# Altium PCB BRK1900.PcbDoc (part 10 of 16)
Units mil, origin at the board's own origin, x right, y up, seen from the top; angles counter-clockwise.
Board outline 8858.27 x 5905.51 mil, 10 copper layers (L1-TOP, L2-GND, L3-PWR, L4-GND, L5-PWR, L6-PWR, L7-GND, L8-SIG, L9-GND, L10-BOT), stack 48.824 mil thick; 456 components, 571 nets, 2296 pads, 2416 vias.
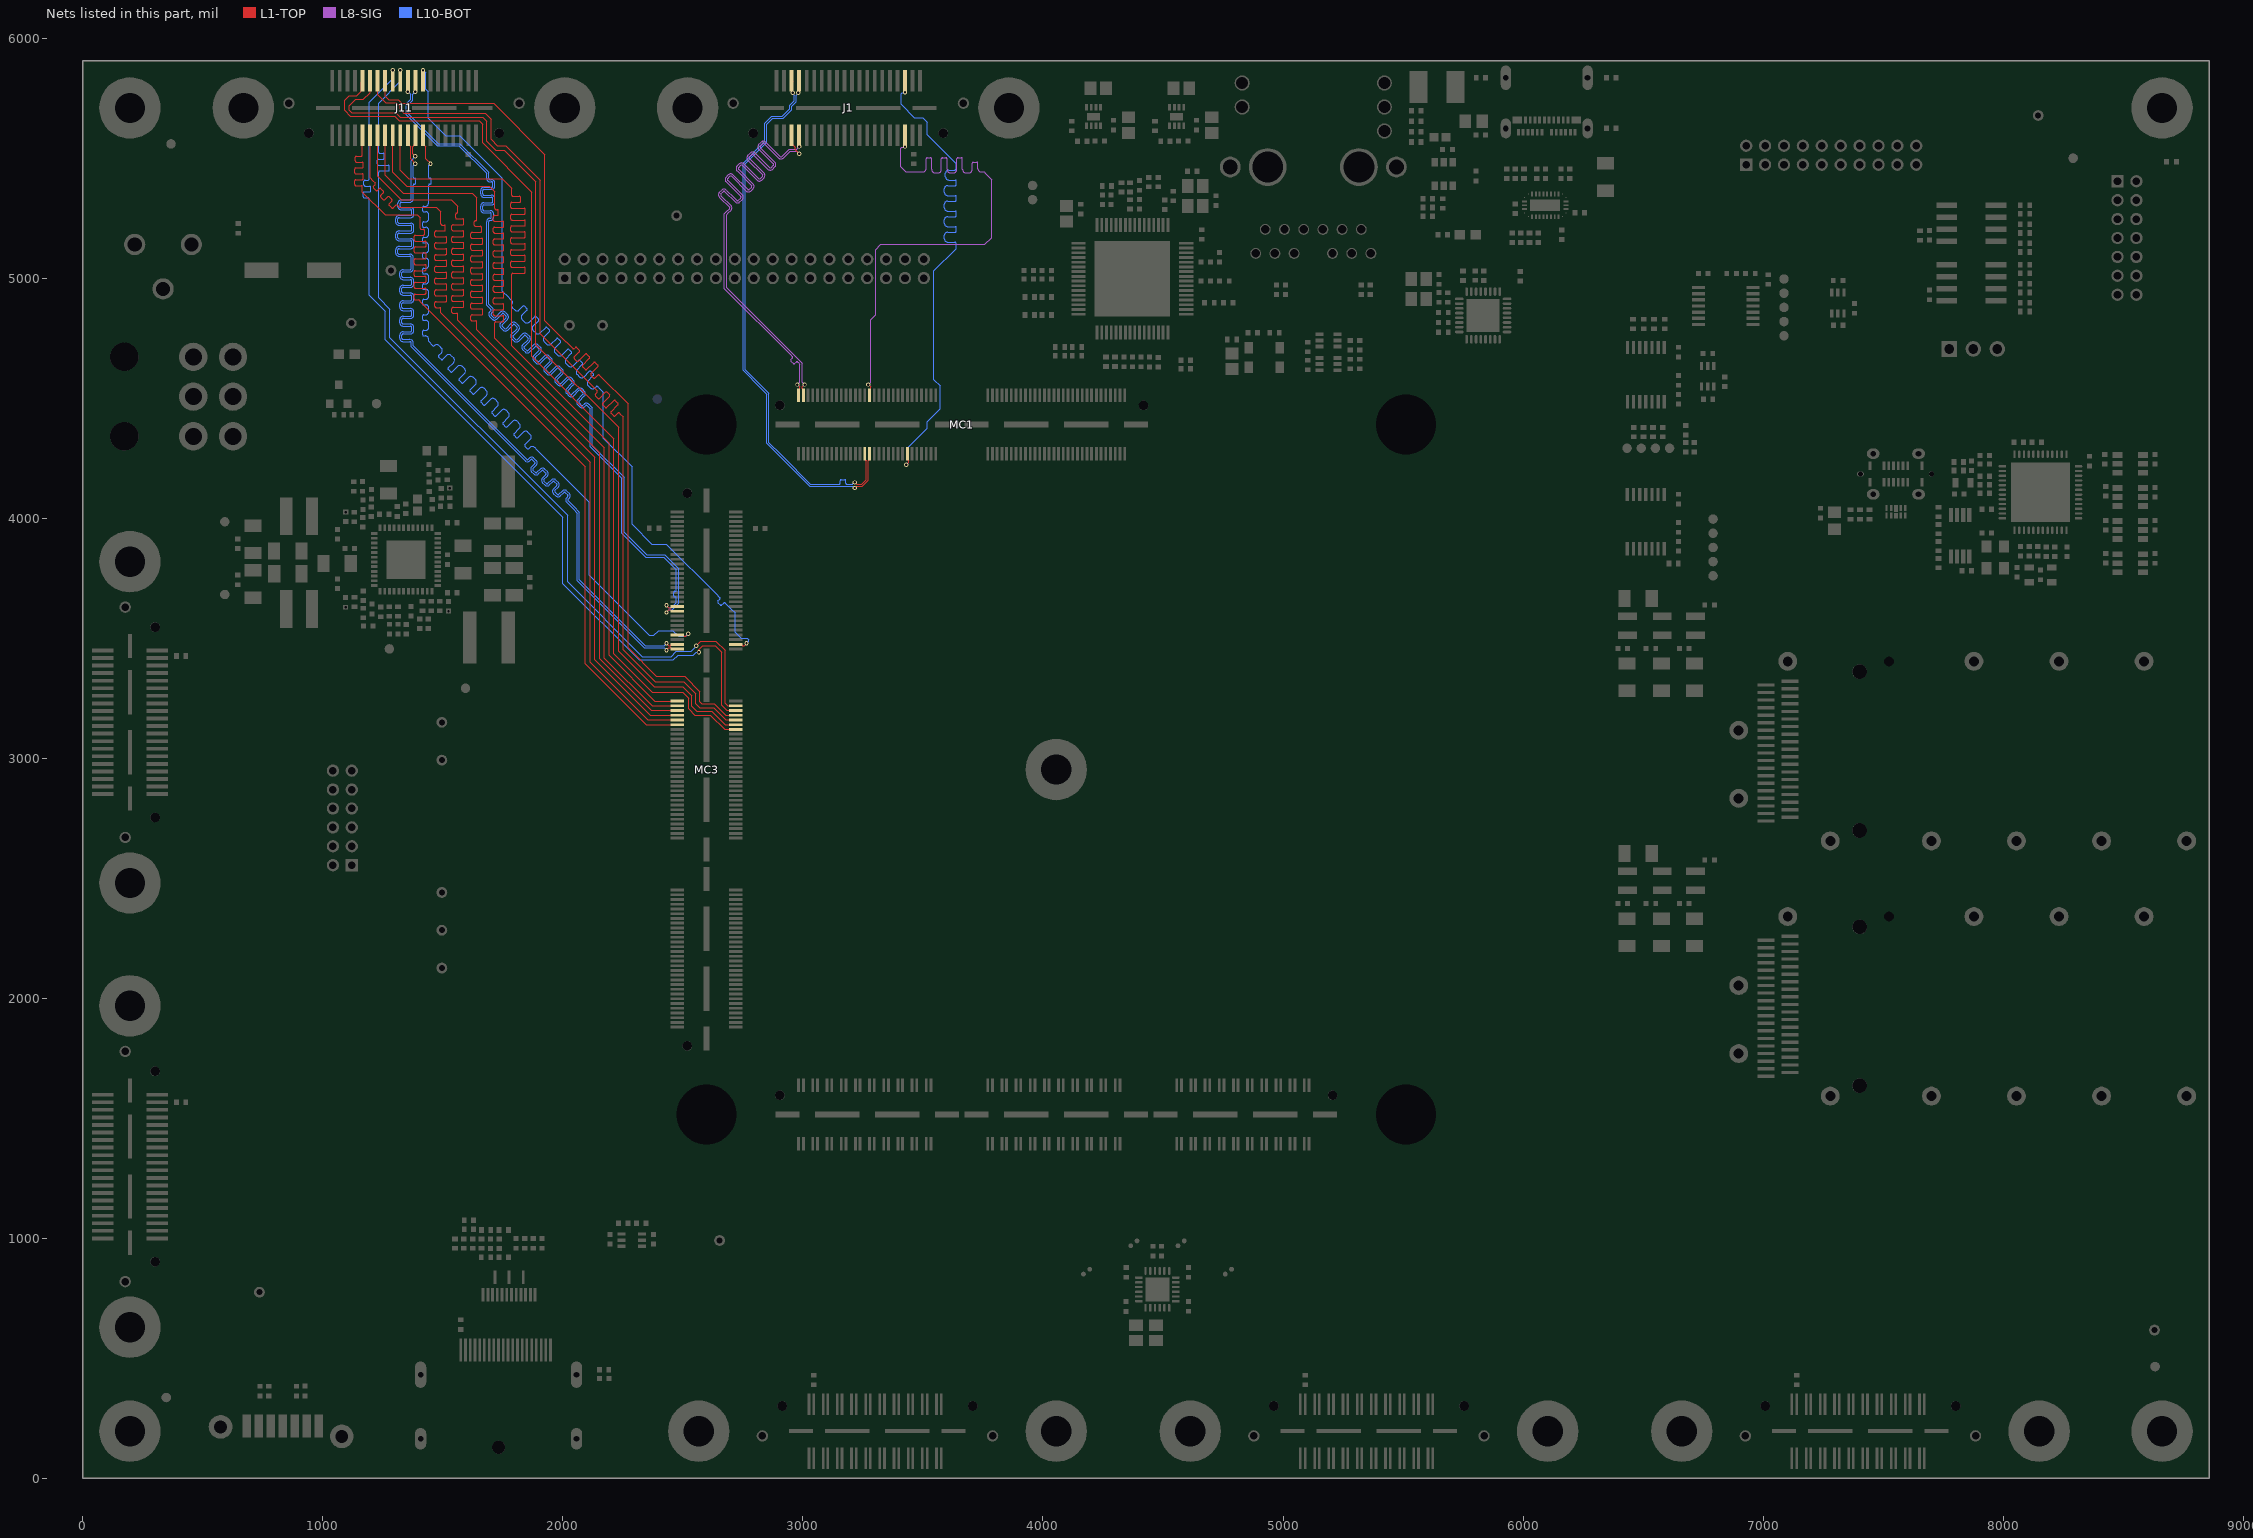
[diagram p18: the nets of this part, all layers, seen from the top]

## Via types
v1: diameter 18, hole 10, L1-TOP to L10-BOT, tented both sides, 2170 vias
v2: diameter 20, hole 10, L1-TOP to L10-BOT, tented both sides, 246 vias

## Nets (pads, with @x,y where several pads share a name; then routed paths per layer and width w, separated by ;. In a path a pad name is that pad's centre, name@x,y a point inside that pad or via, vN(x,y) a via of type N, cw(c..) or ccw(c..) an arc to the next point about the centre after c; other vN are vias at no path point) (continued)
SZG_PORTC_S10_D4N: J11.15 MC3.124 | length 3725.7
  L1-TOP w3.3: MC3.124@2720.08,3474.41 2742.72,3474.41 2748.11,3469.02 2756.01,3469.02 2765.08,3478.09 v1@2765.08,3478.35
  L10-BOT w3.3: v1@1418.37,5866.17 1428.63,5855.9 1428.63,5787.27 1439,5776.9 1439,5666.27 1513.27,5592 1571,5592 1748.03,5414.97 1748.03,4944.88 1758.16,4934.76 1761.19,4931.73 1789.71,4903.2 cw(c1786.42,4899.91) 1789.71,4896.61 ccw(c1799.37,4886.95) 1789.74,4877.27 ; 1789.74,4877.26 1799.57,4867.44 ccw(c1809.26,4877.07) 1818.91,4867.41 1833.95,4882.44 cw(c1837.24,4879.15) 1840.54,4882.44 1850.42,4872.55 cw(c1847.13,4869.26) 1850.42,4865.96 1829.35,4844.89 1829.35,4844.68 ccw(c1840.33,4836.55) 1830.69,4826.87 1840.52,4817.03 ccw(c1850.21,4826.67) 1859.87,4817.01 1882.25,4839.38 cw(c1885.57,4836.11) 1888.86,4839.41 1898.75,4829.52 cw(c1895.45,4826.23) 1898.75,4822.93 1875.03,4799.21 1875.03,4799 ccw(c1886,4790.87) 1876.37,4781.19 1886.2,4771.36 ccw(c1895.89,4780.99) 1905.55,4771.33 1927.93,4793.71 ; 1927.95,4793.73 cw(c1931.25,4790.43) 1934.54,4793.73 1944.43,4783.84 cw(c1941.13,4780.55) 1944.43,4777.25 1920.71,4753.53 1920.71,4753.32 ccw(c1931.68,4745.19) 1922.05,4735.51 1931.88,4725.68 ccw(c1941.57,4735.31) 1951.23,4725.65 1973.61,4748.03 ; 1973.63,4748.05 cw(c1976.92,4744.75) 1980.22,4748.05 1990.1,4738.16 cw(c1986.81,4734.87) 1990.1,4731.57 1966.39,4707.85 1966.39,4707.64 ccw(c1977.36,4699.51) 1967.73,4689.83 1977.56,4680 ccw(c1987.25,4689.63) 1996.91,4679.97 2019.29,4702.35 ; 2019.31,4702.37 cw(c2022.6,4699.08) 2025.9,4702.37 2035.78,4692.49 cw(c2032.49,4689.19) 2035.78,4685.9 2012.06,4662.18 2012.06,4661.96 ccw(c2023.04,4653.83) 2013.41,4644.15 2023.24,4634.32 ; 2023.24,4634.32 ccw(c2032.93,4643.95) 2042.59,4634.29 2064.96,4656.67 ; 2064.99,4656.69 cw(c2068.28,4653.4) 2071.58,4656.69 2081.46,4646.81 cw(c2078.17,4643.51) 2081.46,4640.22 2057.74,4616.5 2057.74,4616.29 ccw(c2068.72,4608.16) 2059.09,4598.47 2068.92,4588.64 ccw(c2078.61,4598.27) 2088.26,4588.61 2110.64,4610.99 cw(c2113.96,4607.72) 2117.26,4611.01 2127.14,4601.13 cw(c2123.85,4597.83) 2127.14,4594.54 2103.42,4570.82 2103.42,4570.61 ccw(c2114.4,4562.48) 2104.77,4552.79 2114.6,4542.96 ccw(c2124.28,4552.59) 2133.94,4542.93 2138.67,4547.66 cw(c2141.96,4544.36) 2145.27,4547.64 ; 2145.29,4547.63 2146.58,4546.34 2149.61,4543.31 2169.29,4523.62 2169.29,4333.73 2289,4214.02 2289,3974.27 2371.27,3892 2431,3892 2635.96,3687.04 2653.6,3669.4 cw(c2650.31,3666.1) 2653.6,3662.81 2645.92,3655.12 ccw(c2649.22,3651.83) 2645.92,3648.53 2655.81,3638.65 ccw(c2659.1,3641.94) 2662.4,3638.65 2670.08,3646.33 cw(c2673.37,3643.04) 2676.67,3646.33 2700.06,3622.94 2717.23,3605.77 2717.23,3569.91 2717.23,3525.05 2742.27,3500 2769,3500 2775,3494 2775,3488.27 v1@2765.08,3478.35
  other v1: 2765.08,3479.35 1417.37,5866.17
SZG_PORTC_S11_D5N: J11.16 MC3.127 | length 3773.6
  L1-TOP w3.3: J11.16@1417.38,5595.86 1417.38,5559 1428.63,5547.75 1428.63,5498 v1@1448.88,5477.75 ; MC3.127@2476.77,3513.78 2499.41,3513.78 2504.8,3508.39 2512.7,3508.39 2521.77,3517.46 v1@2521.77,3517.72
  L10-BOT w3.3: v1@1448.88,5477.75 1441,5469.87 1441,5437.01 1441,5419.78 ccw(c1445.66,5419.78) 1445.66,5415.12 1447.7,5415.12 cw(c1447.7,5410.46) 1452.36,5410.46 1452.36,5396.48 cw(c1447.7,5396.48) 1447.7,5391.82 1445.66,5391.82 ccw(c1445.66,5387.16) 1441,5387.16 1441,5362.2 1441,5354.33 1441,5312.98 cw(c1427.34,5312.98) 1427.34,5299.32 1420.66,5299.32 ccw(c1420.66,5294.66) 1416,5294.66 1416,5280.68 ccw(c1420.66,5280.68) 1420.66,5276.02 1428.27,5276.02 cw(c1428.27,5262.36) 1441.93,5262.36 1441.93,5248.38 cw(c1428.27,5248.38) 1428.27,5234.72 1420.66,5234.72 ccw(c1420.66,5230.06) 1416,5230.06 1416,5216.08 ccw(c1420.66,5216.08) 1420.66,5211.42 1428.27,5211.42 cw(c1428.27,5197.76) 1441.93,5197.76 1441.93,5183.78 cw(c1428.27,5183.78) 1428.27,5170.12 1420.66,5170.12 ccw(c1420.66,5165.46) 1416,5165.46 1416,5151.48 ccw(c1420.66,5151.48) 1420.66,5146.82 1428.27,5146.82 cw(c1428.27,5133.16) 1441.93,5133.16 1441.93,5119.18 cw(c1428.27,5119.18) 1428.27,5105.52 1420.66,5105.52 ccw(c1420.66,5100.86) 1416,5100.86 1416,5086.88 ccw(c1420.66,5086.88) 1420.66,5082.22 1428.27,5082.22 cw(c1428.27,5068.56) 1441.93,5068.56 1441.93,5054.58 cw(c1428.27,5054.58) 1428.27,5040.92 1420.66,5040.92 ccw(c1420.66,5036.26) 1416,5036.26 1416,5022.28 ccw(c1420.66,5022.28) 1420.66,5017.62 1428.27,5017.62 cw(c1428.27,5003.96) 1441.93,5003.96 1441.93,4989.98 cw(c1428.27,4989.98) 1428.27,4976.32 1420.66,4976.32 ccw(c1420.66,4971.66) 1416,4971.66 1416,4957.68 ccw(c1420.66,4957.68) 1420.66,4953.02 1428.27,4953.02 cw(c1428.27,4939.36) 1441.93,4939.36 1441.93,4925.38 cw(c1428.27,4925.38) 1428.27,4911.72 1420.66,4911.72 ccw(c1420.66,4907.06) 1416,4907.06 1416,4893.08 ccw(c1420.66,4893.08) 1420.66,4888.42 1428.27,4888.42 cw(c1428.27,4874.76) 1441.93,4874.76 1441.93,4860.78 cw(c1428.27,4860.78) 1428.27,4847.12 1420.66,4847.12 ccw(c1420.66,4842.46) 1416,4842.46 1416,4828.48 ccw(c1420.66,4828.48) 1420.66,4823.82 1428.27,4823.82 cw(c1428.27,4810.16) 1441.93,4810.16 1441.93,4796.18 cw(c1428.27,4796.18) 1428.27,4782.52 1420.66,4782.52 ccw(c1420.66,4777.86) 1416,4777.86 1416,4763.88 ccw(c1420.66,4763.88) 1420.66,4759.22 1427.34,4759.22 cw(c1427.34,4745.56) 1441,4745.56 1441,4739.41 1441,4736.17 1447.32,4729.85 1450.35,4726.82 1458.77,4718.4 ccw(c1462.06,4721.69) 1465.36,4718.4 cw(c1475.02,4708.74) 1484.68,4718.4 1494.56,4708.51 cw(c1484.9,4698.86) 1494.58,4689.22 1483.21,4677.84 ccw(c1486.5,4674.55) 1483.21,4671.25 1493.09,4661.37 ccw(c1496.39,4664.66) 1499.68,4661.37 1517.08,4678.76 1517.29,4678.76 cw(c1525.42,4667.78) 1535.08,4677.44 1544.96,4667.56 cw(c1535.3,4657.9) 1545,4648.27 1522.58,4625.86 ; 1522.56,4625.84 ccw(c1525.86,4622.54) 1522.56,4619.25 1532.45,4609.36 ccw(c1535.74,4612.66) 1539.04,4609.36 1562.76,4633.08 1562.97,4633.08 cw(c1571.1,4622.11) 1580.76,4631.76 1590.64,4621.88 cw(c1580.98,4612.22) 1590.68,4602.59 1568.26,4580.18 ; 1568.24,4580.16 ccw(c1571.54,4576.86) 1568.24,4573.57 1578.13,4563.68 ccw(c1581.42,4566.98) 1584.72,4563.68 1608.44,4587.4 1608.65,4587.4 cw(c1616.78,4576.43) 1626.43,4586.09 1636.32,4576.2 cw(c1626.66,4566.54) 1636.35,4556.92 1613.94,4534.5 ; 1613.92,4534.48 ccw(c1617.21,4531.19) 1613.92,4527.89 1623.8,4518.01 ccw(c1627.1,4521.3) 1630.39,4518.01 1654.11,4541.72 1654.33,4541.72 cw(c1662.46,4530.75) 1672.11,4540.41 1682,4530.52 cw(c1672.34,4520.86) 1682.03,4511.24 1659.62,4488.82 ; 1659.6,4488.8 ccw(c1662.89,4485.51) 1659.6,4482.21 1669.48,4472.33 ccw(c1672.78,4475.62) 1676.07,4472.33 1699.79,4496.05 1700,4496.05 cw(c1708.13,4485.07) 1717.79,4494.73 1727.68,4484.84 cw(c1718.02,4475.18) 1727.71,4465.56 1705.3,4443.15 ccw(c1708.57,4439.83) 1705.28,4436.53 1715.16,4426.65 ccw(c1718.46,4429.94) 1721.75,4426.65 1745.47,4450.37 1745.68,4450.37 cw(c1753.81,4439.39) 1763.47,4449.05 1773.36,4439.16 cw(c1763.7,4429.5) 1773.39,4419.88 1750.98,4397.47 ; 1750.96,4397.44 ccw(c1754.25,4394.15) 1750.96,4390.85 1760.84,4380.97 ccw(c1764.14,4384.26) 1767.43,4380.97 1791.15,4404.69 1791.36,4404.69 cw(c1799.49,4393.71) 1809.15,4403.37 1819.04,4393.48 cw(c1809.38,4383.83) 1819.07,4374.2 1796.66,4351.79 ; 1796.63,4351.77 ccw(c1799.93,4348.47) 1796.63,4345.18 1806.52,4335.29 ccw(c1809.82,4338.58) 1813.11,4335.29 1836.83,4359.01 1837.04,4359.01 cw(c1845.17,4348.03) 1854.83,4357.69 1864.72,4347.81 cw(c1855.06,4338.15) 1864.75,4328.52 1842.34,4306.11 ; 1842.31,4306.09 ccw(c1845.61,4302.79) 1842.31,4299.5 1852.2,4289.61 ccw(c1855.49,4292.91) 1858.79,4289.61 1863.51,4294.33 cw(c1873.17,4284.68) 1881.3,4295.65 1881.51,4295.65 1882.82,4294.35 ; 1882.83,4294.33 1884.15,4293.02 1887.18,4289.99 2110,4067.17 2110,3762.04 2360.08,3511.96 2379.61,3511.96 2399.53,3531.87 2458.82,3531.87 2482.25,3508.44 2512.49,3508.44 v1@2521.77,3517.72
  other v1: 2521.77,3518.72 1448.88,5476.75
SZG_PORTC_S12_D6P: J11.17 MC3.137 | length 3725.2
  L1-TOP w3.3: v1@2431.77,3608.27 2432.87,3608.27 2442.15,3617.55 2448.79,3617.55 2454.13,3612.2 MC3.137@2476.77,3612.2
  L10-BOT w3.3: v1@1384.89,5776.76 1374.63,5766.5 1374.63,5740.27 1357,5722.64 1357,5684 1481,5560 1570.73,5560 1688.66,5442.07 1691.3,5439.43 1691.3,5421.26 1691.3,5415.11 ccw(c1695.96,5415.11) 1695.96,5410.45 1702.64,5410.45 cw(c1702.64,5396.79) 1716.3,5396.79 1716.3,5382.81 cw(c1702.64,5382.81) 1702.64,5369.15 1670.96,5369.15 ccw(c1670.96,5364.49) 1666.3,5364.49 1666.3,5350.51 ccw(c1670.96,5350.51) 1670.96,5345.85 1702.64,5345.85 cw(c1702.64,5332.19) 1716.3,5332.19 1716.3,5318.21 cw(c1702.64,5318.21) 1702.64,5304.55 1670.96,5304.55 ccw(c1670.96,5299.89) 1666.3,5299.89 1666.3,5285.91 ccw(c1670.96,5285.91) 1670.96,5281.25 1697.81,5281.25 cw(c1697.81,5267.59) 1711.47,5267.59 1711.47,5253.61 cw(c1697.81,5253.61) 1697.81,5239.95 1695.96,5239.95 ccw(c1695.96,5235.29) 1691.3,5235.29 1691.3,5173.23 1691.3,4891.38 1694.33,4888.35 1706.63,4876.05 1707.95,4874.73 1707.95,4874.52 cw(c1696.97,4866.39) 1706.63,4856.73 1701.93,4852.03 ; 1701.91,4852 ccw(c1705.2,4848.71) 1701.91,4845.41 1711.79,4835.53 ccw(c1715.09,4838.82) 1718.38,4835.53 1742.1,4859.25 1742.31,4859.25 cw(c1750.44,4848.27) 1760.1,4857.93 1769.99,4848.05 cw(c1760.33,4838.39) 1770.02,4828.76 1747.61,4806.35 ccw(c1750.88,4803.03) 1747.59,4799.74 1757.47,4789.85 ccw(c1760.77,4793.15) 1764.06,4789.85 1787.78,4813.57 1787.99,4813.57 cw(c1796.12,4802.59) 1805.78,4812.25 1815.67,4802.37 cw(c1806.01,4792.71) 1815.7,4783.08 1793.29,4760.67 ; 1793.26,4760.65 ccw(c1796.56,4757.35) 1793.26,4754.06 1803.15,4744.17 ccw(c1806.45,4747.47) 1809.74,4744.17 1833.46,4767.89 1833.67,4767.89 cw(c1841.8,4756.91) 1851.46,4766.57 1861.34,4756.69 cw(c1851.69,4747.03) 1861.38,4737.4 1838.97,4714.99 ccw(c1842.24,4711.67) 1838.94,4708.38 1848.83,4698.49 ccw(c1852.12,4701.79) 1855.42,4698.49 1879.14,4722.21 1879.35,4722.21 cw(c1887.48,4711.23) 1897.14,4720.89 1907.02,4711.01 cw(c1897.36,4701.35) 1907.06,4691.72 1884.65,4669.31 ; 1884.62,4669.29 ccw(c1887.92,4665.99) 1884.62,4662.7 1894.51,4652.81 ccw(c1897.8,4656.11) 1901.1,4652.81 1924.82,4676.53 1925.03,4676.53 cw(c1933.16,4665.56) 1942.82,4675.21 1952.7,4665.33 cw(c1943.04,4655.67) 1952.74,4646.04 1930.32,4623.63 ; 1930.3,4623.61 ccw(c1933.6,4620.31) 1930.3,4617.02 1940.19,4607.13 ccw(c1943.48,4610.43) 1946.78,4607.13 1970.5,4630.85 1970.71,4630.85 cw(c1978.84,4619.88) 1988.5,4629.54 1998.38,4619.65 cw(c1988.72,4609.99) 1998.42,4600.37 1976,4577.95 ccw(c1979.28,4574.64) 1975.98,4571.34 1985.87,4561.46 ccw(c1989.16,4564.75) 1992.46,4561.46 2016.18,4585.17 2016.39,4585.17 cw(c2024.52,4574.2) 2034.18,4583.86 2044.06,4573.97 cw(c2034.4,4564.31) 2044.09,4554.69 2021.68,4532.27 ; 2021.66,4532.25 ccw(c2024.95,4528.96) 2021.66,4525.66 2031.54,4515.78 ccw(c2034.84,4519.07) 2038.13,4515.78 2061.85,4539.5 2062.07,4539.5 cw(c2070.2,4528.52) 2079.85,4538.18 2089.74,4528.29 cw(c2080.08,4518.63) 2089.77,4509.01 2067.36,4486.6 ccw(c2070.63,4483.28) 2067.34,4479.98 2077.22,4470.1 ccw(c2080.52,4473.39) 2083.81,4470.1 2088.54,4474.82 cw(c2098.2,4465.16) 2106.33,4476.14 2106.54,4476.14 2107.84,4474.83 2109.17,4473.5 2112.2,4470.47 2123.17,4459.5 2123.17,4302.02 2255,4170.2 2255,3940.73 2348.73,3847 2424.73,3847 2482,3789.73 2482,3644.82 2454.73,3617.55 2441.05,3617.55 v1@2431.77,3608.27
  other v1: 2431.77,3607.17 1385.89,5776.76
SZG_PORTC_S13_D7P: J11.18 MC3.121 | length 3774.2
  L1-TOP w3.3: v1(1385.88,5507.28) 1374.63,5518.53 1374.63,5547.62 1385.88,5558.87 J11.18@1385.88,5595.86 ; v1@2431.77,3450.79 2432.87,3450.79 2442.15,3460.07 2448.79,3460.07 2454.13,3454.72 MC3.121@2476.77,3454.72
  L10-BOT w3.3: v1(1385.88,5507.28) 1368,5489.4 1368,5362.2 1368,5330.35 cw(c1363.34,5330.35) 1363.34,5325.69 1326.71,5325.69 ccw(c1326.71,5312.03) 1313.05,5312.03 1313.05,5298.05 ccw(c1326.71,5298.05) 1326.71,5284.39 1366.28,5284.39 cw(c1366.28,5279.73) 1370.94,5279.73 1370.94,5265.75 cw(c1366.28,5265.75) 1366.28,5261.09 1317.78,5261.09 ccw(c1317.78,5247.43) 1304.12,5247.43 1304.12,5233.45 ccw(c1317.78,5233.45) 1317.78,5219.79 1366.28,5219.79 cw(c1366.28,5215.13) 1370.94,5215.13 1370.94,5201.15 cw(c1366.28,5201.15) 1366.28,5196.49 1317.78,5196.49 ccw(c1317.78,5182.83) 1304.12,5182.83 1304.12,5168.85 ccw(c1317.78,5168.85) 1317.78,5155.19 1366.28,5155.19 cw(c1366.28,5150.53) 1370.94,5150.53 1370.94,5136.55 cw(c1366.28,5136.55) 1366.28,5131.89 1317.78,5131.89 ccw(c1317.78,5118.23) 1304.12,5118.23 1304.12,5104.25 ccw(c1317.78,5104.25) 1317.78,5090.59 1363.34,5090.59 cw(c1363.34,5085.93) 1368,5085.93 1368,5079.78 1368,5056.06 1368,5039.58 cw(c1363.34,5039.58) 1363.34,5034.92 1334.35,5034.92 ccw(c1334.35,5021.26) 1320.69,5021.26 1320.69,5007.28 ccw(c1334.35,5007.28) 1334.35,4993.62 1365.26,4993.62 cw(c1365.26,4988.96) 1369.92,4988.96 1369.92,4974.98 cw(c1365.26,4974.98) 1365.26,4970.32 1334.35,4970.32 ccw(c1334.35,4956.66) 1320.69,4956.66 1320.69,4942.68 ccw(c1334.35,4942.68) 1334.35,4929.02 1365.26,4929.02 cw(c1365.26,4924.36) 1369.92,4924.36 1369.92,4910.38 cw(c1365.26,4910.38) 1365.26,4905.72 1334.35,4905.72 ccw(c1334.35,4892.06) 1320.69,4892.06 1320.69,4878.08 ccw(c1334.35,4878.08) 1334.35,4864.42 1365.26,4864.42 cw(c1365.26,4859.76) 1369.92,4859.76 1369.92,4845.78 cw(c1365.26,4845.78) 1365.26,4841.12 1334.35,4841.12 ccw(c1334.35,4827.46) 1320.69,4827.46 1320.69,4813.48 ccw(c1334.35,4813.48) 1334.35,4799.82 1365.26,4799.82 cw(c1365.26,4795.16) 1369.92,4795.16 1369.92,4781.18 cw(c1365.26,4781.18) 1365.26,4776.52 1334.35,4776.52 ccw(c1334.35,4762.86) 1320.69,4762.86 1320.69,4748.88 ccw(c1334.35,4748.88) 1334.35,4735.22 1363.34,4735.22 cw(c1363.34,4730.56) 1368,4730.56 1368,4724.41 1368,4713.47 1838.27,4243.19 1841.31,4240.16 1842.62,4238.84 ccw(c1852.28,4248.5) 1861.94,4238.84 1866.64,4243.55 ; 1866.67,4243.57 cw(c1869.96,4240.27) 1873.26,4243.57 1883.14,4233.68 cw(c1879.85,4230.39) 1883.14,4227.09 1868.02,4211.97 1868.02,4211.76 ccw(c1879,4203.63) 1869.36,4193.95 1879.2,4184.12 ccw(c1888.88,4193.75) 1898.54,4184.09 1912.32,4197.87 ; 1912.34,4197.89 cw(c1915.64,4194.59) 1918.93,4197.89 1928.82,4188 cw(c1925.53,4184.71) 1928.82,4181.41 1913.7,4166.29 1913.7,4166.08 ccw(c1924.68,4157.95) 1915.04,4148.27 ; 1915.05,4148.26 1924.87,4138.44 ccw(c1934.56,4148.07) 1944.22,4138.41 1958,4152.19 cw(c1961.32,4148.92) 1964.61,4152.21 1974.5,4142.33 cw(c1971.2,4139.03) 1974.5,4135.74 1959.38,4120.61 1959.38,4120.4 ccw(c1970.36,4112.27) 1960.72,4102.59 1970.55,4092.76 ccw(c1980.24,4102.39) 1989.9,4092.73 2003.68,4106.51 ; 2003.7,4106.53 cw(c2007,4103.24) 2010.29,4106.53 2020.18,4096.65 cw(c2016.88,4093.35) 2020.18,4090.06 2015.45,4085.33 ccw(c2025.11,4075.67) 2015.45,4066.01 2049.51,4031.95 2052.55,4028.92 2060,4021.47 2060,3739.44 2339.37,3460.07 2422.49,3460.07 v1@2431.77,3450.79
  other v1: 2431.77,3449.69
SZG_PORTC_S14_D6N: J11.19 MC3.139 | length 3725.2
  L1-TOP w3.3: v1@2431.77,3635.83 2432.77,3635.83 2442.05,3626.55 2448.79,3626.55 2454.13,3631.89 MC3.139@2476.77,3631.89
  L10-BOT w3.3: v1@1355.37,5776.76 1365.63,5766.5 1365.63,5744 1348,5726.37 1348,5680.27 1477.27,5551 1567,5551 1682.3,5435.7 1682.3,5421.26 1682.3,5415.11 ccw(c1695.96,5415.11) 1695.96,5401.45 1702.64,5401.45 cw(c1702.64,5396.79) 1707.3,5396.79 1707.3,5382.81 cw(c1702.64,5382.81) 1702.64,5378.15 1670.96,5378.15 ccw(c1670.96,5364.49) 1657.3,5364.49 1657.3,5350.51 ccw(c1670.96,5350.51) 1670.96,5336.85 1702.64,5336.85 cw(c1702.64,5332.19) 1707.3,5332.19 1707.3,5318.21 cw(c1702.64,5318.21) 1702.64,5313.55 1670.96,5313.55 ccw(c1670.96,5299.89) 1657.3,5299.89 1657.3,5285.91 ccw(c1670.96,5285.91) 1670.96,5272.25 1697.81,5272.25 cw(c1697.81,5267.59) 1702.47,5267.59 1702.47,5253.61 cw(c1697.81,5253.61) 1697.81,5248.95 1695.96,5248.95 ccw(c1695.96,5235.29) 1682.3,5235.29 1682.3,5173.23 1682.3,4887.65 1684.93,4885.01 1687.96,4881.98 1700.24,4869.71 cw(c1696.97,4866.39) 1700.27,4863.09 1694.22,4857.05 1694.22,4856.84 ccw(c1705.2,4848.71) 1695.57,4839.02 1705.4,4829.19 ccw(c1715.09,4838.82) 1724.75,4829.17 1747.12,4851.54 ; 1747.15,4851.57 cw(c1750.44,4848.27) 1753.74,4851.57 1763.62,4841.68 cw(c1760.33,4838.39) 1763.62,4835.09 1739.9,4811.37 1739.9,4811.16 ccw(c1750.88,4803.03) 1741.25,4793.35 1751.08,4783.52 ccw(c1760.77,4793.15) 1770.43,4783.49 1792.8,4805.86 ; 1792.83,4805.89 cw(c1796.12,4802.59) 1799.42,4805.89 1809.3,4796 cw(c1806.01,4792.71) 1809.3,4789.41 1785.58,4765.69 1785.58,4765.48 ccw(c1796.56,4757.35) 1786.93,4747.67 1796.76,4737.84 ccw(c1806.45,4747.47) 1816.1,4737.81 1838.48,4760.19 cw(c1841.8,4756.91) 1845.1,4760.21 1854.98,4750.32 cw(c1851.69,4747.03) 1854.98,4743.73 1831.26,4720.01 1831.26,4719.8 ccw(c1842.24,4711.67) 1832.61,4701.99 1842.44,4692.16 ccw(c1852.12,4701.79) 1861.78,4692.13 1884.16,4714.51 ; 1884.18,4714.53 cw(c1887.48,4711.23) 1890.77,4714.53 1900.66,4704.64 cw(c1897.36,4701.35) 1900.66,4698.05 1876.94,4674.33 1876.94,4674.12 ccw(c1887.92,4665.99) 1878.28,4656.31 1888.12,4646.48 ccw(c1897.8,4656.11) 1907.46,4646.45 1929.84,4668.83 cw(c1933.16,4665.56) 1936.45,4668.85 1946.34,4658.97 cw(c1943.04,4655.67) 1946.34,4652.38 1922.62,4628.66 1922.62,4628.44 ccw(c1933.6,4620.31) 1923.96,4610.63 1933.79,4600.8 ccw(c1943.48,4610.43) 1953.14,4600.77 1975.52,4623.15 ; 1975.54,4623.17 cw(c1978.84,4619.88) 1982.13,4623.17 1992.02,4613.29 cw(c1988.72,4609.99) 1992.02,4606.7 1968.3,4582.98 1968.3,4582.77 ccw(c1979.28,4574.64) 1969.64,4564.95 1979.47,4555.12 ccw(c1989.16,4564.75) 1998.82,4555.09 2021.2,4577.47 cw(c2024.52,4574.2) 2027.81,4577.49 2037.7,4567.61 cw(c2034.4,4564.31) 2037.7,4561.02 2013.98,4537.3 2013.98,4537.09 ccw(c2024.95,4528.96) 2015.32,4519.27 2025.15,4509.44 ccw(c2034.84,4519.07) 2044.5,4509.41 2066.88,4531.79 cw(c2070.2,4528.52) 2073.49,4531.81 2083.38,4521.93 cw(c2080.08,4518.63) 2083.38,4515.34 2059.66,4491.62 2059.66,4491.41 ccw(c2070.63,4483.28) 2061,4473.59 2070.83,4463.76 ccw(c2080.52,4473.39) 2090.18,4463.73 2094.9,4468.46 cw(c2098.2,4465.16) 2101.51,4468.44 2102.81,4467.14 2105.84,4464.11 2114.17,4455.78 2114.17,4298.3 2246,4166.47 2246,3937 2345,3838 2421,3838 2473,3786 2473,3751.97 2473,3699.62 cw(c2468.34,3699.62) 2468.34,3694.96 2466.13,3694.96 ccw(c2466.13,3690.3) 2461.47,3690.3 2461.47,3676.32 ccw(c2466.13,3676.32) 2466.13,3671.66 2468.34,3671.66 cw(c2468.34,3667) 2473,3667 2473,3665.35 2473,3648.55 2451,3626.55 2441.05,3626.55 v1@2431.77,3635.83
  other v1: 2431.77,3636.83 1354.37,5776.76
SZG_PORTC_S15_D7N: J11.20 MC3.123 | length 3774.4
  L1-TOP w3.3: J11.20@1354.38,5595.86 1354.38,5559 1365.63,5547.75 1365.63,5497.37 1385.88,5477.12 v1(1385.88,5476.75) ; v1@2431.77,3478.35 2432.77,3478.35 2442.05,3469.07 2448.79,3469.07 2454.13,3474.41 MC3.123@2476.77,3474.41
  L10-BOT w3.3: v1@1385.88,5477.75 1377,5468.87 1377,5440.94 1377,5419.78 ccw(c1381.66,5419.78) 1381.66,5415.12 1383.38,5415.12 cw(c1383.38,5410.46) 1388.04,5410.46 1388.04,5396.48 cw(c1383.38,5396.48) 1383.38,5391.82 1381.66,5391.82 ccw(c1381.66,5387.16) 1377,5387.16 1377,5362.2 1377,5330.35 cw(c1363.34,5330.35) 1363.34,5316.69 1326.71,5316.69 ccw(c1326.71,5312.03) 1322.05,5312.03 1322.05,5298.05 ccw(c1326.71,5298.05) 1326.71,5293.39 1366.28,5293.39 cw(c1366.28,5279.73) 1379.94,5279.73 1379.94,5265.75 cw(c1366.28,5265.75) 1366.28,5252.09 1317.78,5252.09 ccw(c1317.78,5247.43) 1313.12,5247.43 1313.12,5233.45 ccw(c1317.78,5233.45) 1317.78,5228.79 1366.28,5228.79 cw(c1366.28,5215.13) 1379.94,5215.13 1379.94,5201.15 cw(c1366.28,5201.15) 1366.28,5187.49 1317.78,5187.49 ccw(c1317.78,5182.83) 1313.12,5182.83 1313.12,5168.85 ccw(c1317.78,5168.85) 1317.78,5164.19 1366.28,5164.19 cw(c1366.28,5150.53) 1379.94,5150.53 1379.94,5136.55 cw(c1366.28,5136.55) 1366.28,5122.89 1317.78,5122.89 ccw(c1317.78,5118.23) 1313.12,5118.23 1313.12,5104.25 ccw(c1317.78,5104.25) 1317.78,5099.59 1363.34,5099.59 cw(c1363.34,5085.93) 1377,5085.93 1377,5079.78 1377,5056.06 1377,5039.58 cw(c1363.34,5039.58) 1363.34,5025.92 1334.35,5025.92 ccw(c1334.35,5021.26) 1329.69,5021.26 1329.69,5007.28 ccw(c1334.35,5007.28) 1334.35,5002.62 1365.26,5002.62 cw(c1365.26,4988.96) 1378.92,4988.96 1378.92,4974.98 cw(c1365.26,4974.98) 1365.26,4961.32 1334.35,4961.32 ccw(c1334.35,4956.66) 1329.69,4956.66 1329.69,4942.68 ccw(c1334.35,4942.68) 1334.35,4938.02 1365.26,4938.02 cw(c1365.26,4924.36) 1378.92,4924.36 1378.92,4910.38 cw(c1365.26,4910.38) 1365.26,4896.72 1334.35,4896.72 ccw(c1334.35,4892.06) 1329.69,4892.06 1329.69,4878.08 ccw(c1334.35,4878.08) 1334.35,4873.42 1365.26,4873.42 cw(c1365.26,4859.76) 1378.92,4859.76 1378.92,4845.78 cw(c1365.26,4845.78) 1365.26,4832.12 1334.35,4832.12 ccw(c1334.35,4827.46) 1329.69,4827.46 1329.69,4813.48 ccw(c1334.35,4813.48) 1334.35,4808.82 1365.26,4808.82 cw(c1365.26,4795.16) 1378.92,4795.16 1378.92,4781.18 cw(c1365.26,4781.18) 1365.26,4767.52 1334.35,4767.52 ccw(c1334.35,4762.86) 1329.69,4762.86 1329.69,4748.88 ccw(c1334.35,4748.88) 1334.35,4744.22 1363.34,4744.22 cw(c1363.34,4730.56) 1377,4730.56 1377,4724.41 1377,4717.2 1844.64,4249.56 1847.67,4246.53 1848.99,4245.21 ccw(c1852.28,4248.5) 1855.58,4245.21 1861.62,4251.25 1861.83,4251.25 cw(c1869.96,4240.27) 1879.62,4249.93 1889.51,4240.05 cw(c1879.85,4230.39) 1889.54,4220.76 1875.72,4206.95 ccw(c1879,4203.63) 1875.7,4200.34 1885.59,4190.45 ccw(c1888.88,4193.75) 1892.18,4190.45 1907.3,4205.57 1907.51,4205.57 cw(c1915.64,4194.59) 1925.3,4204.25 1935.18,4194.37 cw(c1925.53,4184.71) 1935.22,4175.08 1921.4,4161.27 ; 1921.38,4161.25 ccw(c1924.68,4157.95) 1921.38,4154.66 1931.27,4144.77 ccw(c1934.56,4148.07) 1937.86,4144.77 1952.98,4159.89 1953.19,4159.89 cw(c1961.32,4148.92) 1970.98,4158.57 1980.86,4148.69 cw(c1971.2,4139.03) 1980.9,4129.4 1967.08,4115.59 ; 1967.06,4115.57 ccw(c1970.36,4112.27) 1967.06,4108.98 1976.95,4099.09 ccw(c1980.24,4102.39) 1983.54,4099.09 1998.66,4114.21 1998.87,4114.21 cw(c2007,4103.24) 2016.66,4112.9 2026.54,4103.01 cw(c2016.88,4093.35) 2026.58,4083.73 2021.82,4078.97 ccw(c2025.11,4075.67) 2021.82,4072.38 2055.88,4038.32 2058.91,4035.29 2069,4025.2 2069,3743.17 2343.1,3469.07 2422.49,3469.07 v1@2431.77,3478.35
  other v1: 2431.77,3479.35
SZG_PORTC_S16: J11.21 MC3.118 | length 3726.8
  L1-TOP w4.55: v1(2555.12,3468.5) 2574.8,3488.19 2637.8,3488.19 2677.17,3448.82 2677.17,3228.35 2687.01,3218.5 MC3.118@2720.08,3218.5
  L10-BOT w4.55: v1(1322.89,5866.17) 1322.88,5818.95 1232.28,5728.35 1232.28,5546.31 1232.28,5524.66 ccw(c1237.19,5524.66) 1237.19,5519.75 1251.51,5519.75 cw(c1251.51,5514.84) 1256.42,5514.84 1256.42,5500.11 cw(c1251.51,5500.11) 1251.51,5495.2 1231.02,5495.2 ccw(c1231.02,5490.29) 1226.11,5490.29 1226.11,5475.56 ccw(c1231.02,5475.56) 1231.02,5470.65 1272.34,5470.65 cw(c1272.34,5465.74) 1277.25,5465.74 1277.25,5451.01 cw(c1272.34,5451.01) 1272.34,5446.1 1237.19,5446.1 ccw(c1237.19,5441.19) 1232.28,5441.19 1232.28,5414.37 1232.28,4917.6 1279.53,4870.36 1279.53,4752.25 2019.69,4012.09 2019.69,3735.23 2331.21,3423.7 2451.26,3423.7 2472.44,3444.88 2533.87,3444.88 2555.12,3466.13 v1(2555.12,3468.5)
SZG_PORTC_S17: J11.22 MC3.119 | length 3866.4
  L1-TOP w4.55: J11.22@1322.88,5595.86 1322.88,5448.77 1358.27,5413.39 1748.03,5413.39 1787.4,5374.02 1787.4,5364.3 1787.4,5344.91 ccw(c1792.31,5344.91) 1792.31,5340 1819.31,5340 cw(c1819.31,5335.09) 1824.22,5335.09 1824.22,5320.36 cw(c1819.31,5320.36) 1819.31,5315.45 1787.82,5315.45 ccw(c1787.82,5310.54) 1782.91,5310.54 1782.91,5295.81 ccw(c1787.82,5295.81) 1787.82,5290.9 1839.06,5290.9 cw(c1839.06,5285.99) 1843.97,5285.99 1843.97,5271.26 cw(c1839.06,5271.26) 1839.06,5266.35 1787.82,5266.35 ccw(c1787.82,5261.44) 1782.91,5261.44 1782.91,5246.71 ccw(c1787.82,5246.71) 1787.82,5241.8 1839.06,5241.8 cw(c1839.06,5236.89) 1843.97,5236.89 1843.97,5222.16 cw(c1839.06,5222.16) 1839.06,5217.25 1787.82,5217.25 ccw(c1787.82,5212.34) 1782.91,5212.34 1782.91,5197.61 ccw(c1787.82,5197.61) 1787.82,5192.7 1839.06,5192.7 cw(c1839.06,5187.79) 1843.97,5187.79 1843.97,5173.06 cw(c1839.06,5173.06) 1839.06,5168.15 1787.82,5168.15 ccw(c1787.82,5163.24) 1782.91,5163.24 1782.91,5148.51 ccw(c1787.82,5148.51) 1787.82,5143.6 1839.06,5143.6 cw(c1839.06,5138.69) 1843.97,5138.69 1843.97,5123.96 cw(c1839.06,5123.96) 1839.06,5119.05 1787.82,5119.05 ccw(c1787.82,5114.14) 1782.91,5114.14 1782.91,5099.41 ccw(c1787.82,5099.41) 1787.82,5094.5 1839.06,5094.5 cw(c1839.06,5089.59) 1843.97,5089.59 1843.97,5074.86 cw(c1839.06,5074.86) 1839.06,5069.95 1787.82,5069.95 ccw(c1787.82,5065.04) 1782.91,5065.04 1782.91,5050.31 ccw(c1787.82,5050.31) 1787.82,5045.4 1839.06,5045.4 cw(c1839.06,5040.49) 1843.97,5040.49 1843.97,5025.76 cw(c1839.06,5025.76) 1839.06,5020.85 1792.31,5020.85 ccw(c1792.31,5015.94) 1787.4,5015.94 1787.4,4989.12 1787.4,4717.38 2192.8,4311.98 2192.8,3428.2 2382.81,3238.19 MC3.119@2476.77,3238.19
SZG_PORTC_S18: J11.23 MC3.116 | length 3726.8
  L1-TOP w4.55: v1(2566.93,3440.94) 2566.93,3452.76 2582.68,3468.5 2633.86,3468.5 2661.42,3440.94 2661.42,3220.47 2683.07,3198.82 MC3.116@2720.08,3198.82
  L10-BOT w4.55: v1(1291.37,5866.17) 1291.38,5830.75 1192.91,5732.28 1192.91,5449.65 1192.91,5412.76 cw(c1188,5412.76) 1188,5407.85 1176.44,5407.85 ccw(c1176.44,5402.94) 1171.53,5402.94 1171.53,5388.21 ccw(c1176.44,5388.21) 1176.44,5383.3 1194.91,5383.3 cw(c1194.91,5378.39) 1199.82,5378.39 1199.82,5363.66 cw(c1194.91,5363.66) 1194.91,5358.75 1173.36,5358.75 ccw(c1173.36,5353.84) 1168.45,5353.84 1168.45,5339.11 ccw(c1173.36,5339.11) 1173.36,5334.2 1188,5334.2 cw(c1188,5329.29) 1192.91,5329.29 1192.91,5327.01 1192.91,4929.13 1259.84,4862.2 1259.84,4744.09 2000,4003.94 2000,3727.08 2317.63,3409.45 2460.63,3409.45 2480.32,3429.13 2543.33,3429.13 2555.14,3440.94 v1(2566.93,3440.94)
SZG_PORTC_S19: J11.24 MC3.117 | length 3866.4
  L1-TOP w4.55: J11.24@1291.38,5595.86 1291.38,5440.9 1350.39,5381.89 1693.32,5381.89 1716.54,5358.67 1716.54,5331.43 1716.54,5290.5 ccw(c1721.45,5290.5) 1721.45,5285.59 1726.89,5285.59 cw(c1726.89,5280.68) 1731.8,5280.68 1731.8,5265.95 cw(c1726.89,5265.95) 1726.89,5261.04 1715.78,5261.04 ccw(c1715.78,5256.13) 1710.87,5256.13 1710.87,5241.4 ccw(c1715.78,5241.4) 1715.78,5236.49 1749.81,5236.49 cw(c1749.81,5231.58) 1754.72,5231.58 1754.72,5216.85 cw(c1749.81,5216.85) 1749.81,5211.94 1715.78,5211.94 ccw(c1715.78,5207.03) 1710.87,5207.03 1710.87,5192.3 ccw(c1715.78,5192.3) 1715.78,5187.39 1749.81,5187.39 cw(c1749.81,5182.48) 1754.72,5182.48 1754.72,5167.75 cw(c1749.81,5167.75) 1749.81,5162.84 1715.78,5162.84 ccw(c1715.78,5157.93) 1710.87,5157.93 1710.87,5143.2 ccw(c1715.78,5143.2) 1715.78,5138.29 1749.81,5138.29 cw(c1749.81,5133.38) 1754.72,5133.38 1754.72,5118.65 cw(c1749.81,5118.65) 1749.81,5113.74 1715.78,5113.74 ccw(c1715.78,5108.83) 1710.87,5108.83 1710.87,5094.1 ccw(c1715.78,5094.1) 1715.78,5089.19 1749.81,5089.19 cw(c1749.81,5084.28) 1754.72,5084.28 1754.72,5069.55 cw(c1749.81,5069.55) 1749.81,5064.64 1715.78,5064.64 ccw(c1715.78,5059.73) 1710.87,5059.73 1710.87,5045 ccw(c1715.78,5045) 1715.78,5040.09 1749.81,5040.09 cw(c1749.81,5035.18) 1754.72,5035.18 1754.72,5020.45 cw(c1749.81,5020.45) 1749.81,5015.54 1715.78,5015.54 ccw(c1715.78,5010.63) 1710.87,5010.63 1710.87,4995.9 ccw(c1715.78,4995.9) 1715.78,4990.99 1749.81,4990.99 cw(c1749.81,4986.08) 1754.72,4986.08 1754.72,4971.35 cw(c1749.81,4971.35) 1749.81,4966.44 1715.78,4966.44 ccw(c1715.78,4961.53) 1710.87,4961.53 1710.87,4946.8 ccw(c1715.78,4946.8) 1715.78,4941.89 1749.81,4941.89 cw(c1749.81,4936.98) 1754.72,4936.98 1754.72,4922.25 cw(c1749.81,4922.25) 1749.81,4917.34 1715.78,4917.34 ccw(c1715.78,4912.43) 1710.87,4912.43 1710.87,4897.7 ccw(c1715.78,4897.7) 1715.78,4892.79 1749.81,4892.79 cw(c1749.81,4887.88) 1754.72,4887.88 1754.72,4873.15 cw(c1749.81,4873.15) 1749.81,4868.24 1715.78,4868.24 ccw(c1715.78,4863.33) 1710.87,4863.33 1710.87,4848.6 ccw(c1715.78,4848.6) 1715.78,4843.69 1749.81,4843.69 cw(c1749.81,4838.78) 1754.72,4838.78 1754.72,4824.05 cw(c1749.81,4824.05) 1749.81,4819.14 1721.45,4819.14 ccw(c1721.45,4814.23) 1716.54,4814.23 1716.54,4787.4 1716.54,4748.87 2173.11,4292.3 2173.11,3416.89 2371.5,3218.5 MC3.117@2476.77,3218.5
SZG_PORTC_S20: J11.25 MC3.114 | length 3866.4
  L1-TOP w4.55: J11.25@1259.88,5821.46 1259.88,5758.12 1275.07,5742.93 1314.18,5742.93 1328.65,5728.47 1711.25,5728.47 1925.2,5514.52 1925.2,4822.83 2012.26,4735.77 2013.87,4734.16 2041.2,4706.83 ccw(c2044.67,4710.3) 2048.14,4706.83 2051.28,4709.97 cw(c2054.75,4706.49) 2058.22,4709.97 2068.64,4699.55 cw(c2065.16,4696.08) 2068.64,4692.61 2047.82,4671.8 ccw(c2051.3,4668.32) 2047.82,4664.85 2058.24,4654.44 ccw(c2061.71,4657.91) 2065.18,4654.44 2093.6,4682.85 cw(c2097.07,4679.38) 2100.54,4682.85 2110.95,4672.43 cw(c2107.48,4668.96) 2110.95,4665.49 2082.54,4637.08 ccw(c2086.02,4633.6) 2082.54,4630.13 2092.96,4619.72 ccw(c2096.43,4623.19) 2099.9,4619.72 2128.31,4648.13 cw(c2131.79,4644.66) 2135.26,4648.13 2145.67,4637.71 cw(c2142.2,4634.24) 2145.67,4630.77 2117.26,4602.36 ccw(c2120.73,4598.89) 2117.26,4595.41 2127.68,4585 ccw(c2131.15,4588.47) 2134.62,4585 2145.36,4595.73 cw(c2148.83,4592.26) 2152.3,4595.73 2153.91,4594.12 2271.54,4476.5 2271.54,3459.46 2390,3341 2507,3341 2571.11,3276.89 2571.11,3234.84 2579.61,3226.35 2631.65,3226.35 2678.87,3179.13 MC3.114@2720.08,3179.13
SZG_PORTC_S21: J11.26 MC3.115 | length 3866.4
  L1-TOP w4.55: J11.26@1259.88,5595.86 1259.88,5429.09 1334.65,5354.33 1622.27,5354.33 1641.73,5334.87 1641.73,5314.55 1641.73,5244.41 cw(c1636.82,5244.41) 1636.82,5239.5 ccw(c1636.82,5234.59) 1631.91,5234.59 1631.91,5219.86 ccw(c1636.82,5219.86) 1636.82,5214.95 1656.52,5214.95 cw(c1656.52,5210.04) 1661.43,5210.04 1661.43,5195.31 cw(c1656.52,5195.31) 1656.52,5190.4 1621.64,5190.4 ccw(c1621.64,5185.49) 1616.73,5185.49 1616.73,5170.76 ccw(c1621.64,5170.76) 1621.64,5165.85 1661.82,5165.85 cw(c1661.82,5160.94) 1666.73,5160.94 1666.73,5146.21 cw(c1661.82,5146.21) 1661.82,5141.3 1621.64,5141.3 ccw(c1621.64,5136.39) 1616.73,5136.39 1616.73,5121.66 ccw(c1621.64,5121.66) 1621.64,5116.75 1661.82,5116.75 cw(c1661.82,5111.84) 1666.73,5111.84 1666.73,5097.11 cw(c1661.82,5097.11) 1661.82,5092.2 1621.64,5092.2 ccw(c1621.64,5087.29) 1616.73,5087.29 1616.73,5072.56 ccw(c1621.64,5072.56) 1621.64,5067.65 1661.82,5067.65 cw(c1661.82,5062.74) 1666.73,5062.74 1666.73,5048.01 cw(c1661.82,5048.01) 1661.82,5043.1 1621.64,5043.1 ccw(c1621.64,5038.19) 1616.73,5038.19 1616.73,5023.46 ccw(c1621.64,5023.46) 1621.64,5018.55 1661.82,5018.55 cw(c1661.82,5013.64) 1666.73,5013.64 1666.73,4998.91 cw(c1661.82,4998.91) 1661.82,4994 1621.64,4994 ccw(c1621.64,4989.09) 1616.73,4989.09 1616.73,4974.36 ccw(c1621.64,4974.36) 1621.64,4969.45 1661.82,4969.45 cw(c1661.82,4964.54) 1666.73,4964.54 1666.73,4949.81 cw(c1661.82,4949.81) 1661.82,4944.9 1621.64,4944.9 ccw(c1621.64,4939.99) 1616.73,4939.99 1616.73,4925.26 ccw(c1621.64,4925.26) 1621.64,4920.35 1661.82,4920.35 cw(c1661.82,4915.44) 1666.73,4915.44 1666.73,4900.71 cw(c1661.82,4900.71) 1661.82,4895.8 1621.64,4895.8 ccw(c1621.64,4890.89) 1616.73,4890.89 1616.73,4876.16 ccw(c1621.64,4876.16) 1621.64,4871.25 1661.82,4871.25 cw(c1661.82,4866.34) 1666.73,4866.34 1666.73,4851.61 cw(c1661.82,4851.61) 1661.82,4846.7 1621.64,4846.7 ccw(c1621.64,4841.79) 1616.73,4841.79 1616.73,4827.06 ccw(c1621.64,4827.06) 1621.64,4822.15 1636.82,4822.15 cw(c1636.82,4817.24) 1641.73,4817.24 1641.73,4814.96 1641.73,4784.31 2153.43,4272.61 2153.43,3413.57 2368.18,3198.82 MC3.115@2476.77,3198.82
SZG_PORTC_S22: J11.27 MC3.112 | length 3866.4
  L1-TOP w4.55: J11.27@1228.38,5821.46 1228.38,5763.74 1262.1,5730.03 1307.03,5730.03 1322.26,5714.8 1322.26,5702.85 1338.11,5687 1676,5687 1701.04,5661.96 1701.04,5577.37 1727.26,5551.15 1762.58,5551.15 1905.48,5408.25 1905.48,4767.75 2113.85,4559.38 2115.46,4557.77 2142.42,4530.81 cw(c2138.95,4527.34) 2142.42,4523.87 2135.47,4516.92 ccw(c2138.95,4513.45) 2135.47,4509.98 2145.89,4499.56 ccw(c2149.36,4503.03) 2152.83,4499.56 2177.46,4524.18 cw(c2180.93,4520.71) 2184.4,4524.18 2194.82,4513.77 cw(c2191.34,4510.3) 2194.82,4506.82 2166.4,4478.41 ccw(c2169.88,4474.94) 2166.4,4471.47 2176.82,4461.05 ccw(c2180.29,4464.53) 2183.76,4461.05 2212.17,4489.47 cw(c2215.65,4485.99) 2219.12,4489.47 2229.53,4479.05 cw(c2226.06,4475.58) 2229.53,4472.11 2201.12,4443.69 ccw(c2204.59,4440.22) 2201.12,4436.75 2211.54,4426.33 ccw(c2215.01,4429.81) 2218.48,4426.33 2229.22,4437.07 cw(c2232.69,4433.6) 2236.16,4437.07 2237.77,4435.46 2251.85,4421.38 2251.85,3451.15 2384,3319 2503,3319 2553.94,3268.06 2553.94,3226.88 2569.82,3211 2628,3211 2679.55,3159.45 MC3.112@2720.08,3159.45
SZG_PORTC_S23: J11.28 MC3.113 | length 3866.4
  L1-TOP w4.55: J11.28@1228.38,5595.86 1228.38,5425.16 1326.77,5326.77 1536.13,5326.77 1562.8,5300.1 1562.99,5299.91 1562.99,5275.9 cw(c1558.08,5275.9) 1558.08,5270.99 ccw(c1558.08,5266.08) 1553.17,5266.08 1553.17,5251.35 ccw(c1558.08,5251.35) 1558.08,5246.44 1583.07,5246.44 cw(c1583.07,5241.53) 1587.98,5241.53 1587.98,5226.8 cw(c1583.07,5226.8) 1583.07,5221.89 1542.9,5221.89 ccw(c1542.9,5216.98) 1537.99,5216.98 1537.99,5202.25 ccw(c1542.9,5202.25) 1542.9,5197.34 1583.08,5197.34 cw(c1583.08,5192.43) 1587.99,5192.43 1587.99,5177.7 cw(c1583.08,5177.7) 1583.08,5172.79 1542.9,5172.79 ccw(c1542.9,5167.88) 1537.99,5167.88 1537.99,5153.15 ccw(c1542.9,5153.15) 1542.9,5148.24 1583.08,5148.24 cw(c1583.08,5143.33) 1587.99,5143.33 1587.99,5128.6 cw(c1583.08,5128.6) 1583.08,5123.69 1542.9,5123.69 ccw(c1542.9,5118.78) 1537.99,5118.78 1537.99,5104.05 ccw(c1542.9,5104.05) 1542.9,5099.14 1583.08,5099.14 cw(c1583.08,5094.23) 1587.99,5094.23 1587.99,5079.5 cw(c1583.08,5079.5) 1583.08,5074.59 1542.9,5074.59 ccw(c1542.9,5069.68) 1537.99,5069.68 1537.99,5054.95 ccw(c1542.9,5054.95) 1542.9,5050.04 1583.08,5050.04 cw(c1583.08,5045.13) 1587.99,5045.13 1587.99,5030.4 cw(c1583.08,5030.4) 1583.08,5025.49 1542.9,5025.49 ccw(c1542.9,5020.58) 1537.99,5020.58 1537.99,5005.85 ccw(c1542.9,5005.85) 1542.9,5000.94 1583.08,5000.94 cw(c1583.08,4996.03) 1587.99,4996.03 1587.99,4981.3 cw(c1583.08,4981.3) 1583.08,4976.39 1542.9,4976.39 ccw(c1542.9,4971.48) 1537.99,4971.48 1537.99,4956.75 ccw(c1542.9,4956.75) 1542.9,4951.84 1583.08,4951.84 cw(c1583.08,4946.93) 1587.99,4946.93 1587.99,4932.2 cw(c1583.08,4932.2) 1583.08,4927.29 1542.9,4927.29 ccw(c1542.9,4922.38) 1537.99,4922.38 1537.99,4907.65 ccw(c1542.9,4907.65) 1542.9,4902.74 1583.08,4902.74 cw(c1583.08,4897.83) 1587.99,4897.83 1587.99,4883.1 cw(c1583.08,4883.1) 1583.08,4878.19 1542.9,4878.19 ccw(c1542.9,4873.28) 1537.99,4873.28 1537.99,4858.55 ccw(c1542.9,4858.55) 1542.9,4853.64 1558.08,4853.64 cw(c1558.08,4848.73) 1562.99,4848.73 1562.99,4846.46 1562.99,4823.68 2133.74,4252.93 2133.74,3409.26 2363.87,3179.13 MC3.113@2476.77,3179.13
SZG_PORTC_S24: J11.29 MC3.110 | length 3864.8
  L1-TOP w4.55: J11.29@1196.88,5821.46 1196.88,5771.69 1169.29,5744.09 1137.09,5744.09 1111,5718 1111,5698.08 1119.78,5689.3 1303.31,5689.3 1322.62,5670 1667,5670 1684.07,5652.93 1684.07,5569.01 1719.84,5533.23 1755.16,5533.23 1887.56,5400.83 1887.56,4722.67 2232.17,4378.07 2232.17,3445.83 2380,3298 2499,3298 2537.44,3259.56 2537.44,3215.69 2558.13,3195 2621,3195 2676.24,3139.76 MC3.110@2720.08,3139.76
SZG_PORTC_S25: J11.30 MC3.111 | length 3866.4
  L1-TOP w4.55: J11.30@1196.88,5595.86 1196.88,5417.29 1206.69,5407.48 1208.3,5405.87 1217.64,5396.53 cw(c1214.17,5393.06) 1217.64,5389.59 1211.31,5383.26 ccw(c1214.79,5379.79) 1211.31,5376.32 1221.73,5365.9 ccw(c1225.2,5369.37) 1228.67,5365.9 1235.28,5372.51 cw(c1238.75,5369.04) 1242.23,5372.51 1252.64,5362.09 cw(c1249.17,5358.62) 1252.64,5355.15 1241.74,5344.25 ccw(c1245.21,5340.78) 1241.74,5337.3 1252.16,5326.89 ccw(c1255.63,5330.36) 1259.1,5326.89 1270,5337.79 cw(c1273.47,5334.32) 1276.95,5337.79 1287.36,5327.37 cw(c1283.89,5323.9) 1287.36,5320.43 1276.46,5309.53 ccw(c1279.93,5306.06) 1276.46,5302.58 1286.87,5292.17 ccw(c1290.35,5295.64) 1293.82,5292.17 1304.44,5302.79 cw(c1307.91,5299.32) 1311.38,5302.79 1312.99,5301.18 1318.9,5295.28 1473.48,5295.28 1492.13,5276.63 1492.13,5272.43 1492.13,5225.87 ccw(c1497.04,5225.87) 1497.04,5220.96 1505.76,5220.96 cw(c1505.76,5216.05) 1510.67,5216.05 1510.67,5201.32 cw(c1505.76,5201.32) 1505.76,5196.41 1472.04,5196.41 ccw(c1472.04,5191.5) 1467.13,5191.5 1467.13,5176.77 ccw(c1472.04,5176.77) 1472.04,5171.86 1512.22,5171.86 cw(c1512.22,5166.95) 1517.13,5166.95 1517.13,5152.22 cw(c1512.22,5152.22) 1512.22,5147.31 1472.04,5147.31 ccw(c1472.04,5142.4) 1467.13,5142.4 1467.13,5127.67 ccw(c1472.04,5127.67) 1472.04,5122.76 1512.22,5122.76 cw(c1512.22,5117.85) 1517.13,5117.85 1517.13,5103.12 cw(c1512.22,5103.12) 1512.22,5098.21 1472.04,5098.21 ccw(c1472.04,5093.3) 1467.13,5093.3 1467.13,5078.57 ccw(c1472.04,5078.57) 1472.04,5073.66 1512.22,5073.66 cw(c1512.22,5068.75) 1517.13,5068.75 1517.13,5054.02 cw(c1512.22,5054.02) 1512.22,5049.11 1472.04,5049.11 ccw(c1472.04,5044.2) 1467.13,5044.2 1467.13,5029.47 ccw(c1472.04,5029.47) 1472.04,5024.56 1512.22,5024.56 cw(c1512.22,5019.65) 1517.13,5019.65 1517.13,5004.92 cw(c1512.22,5004.92) 1512.22,5000.01 1472.04,5000.01 ccw(c1472.04,4995.1) 1467.13,4995.1 1467.13,4980.37 ccw(c1472.04,4980.37) 1472.04,4975.46 1512.22,4975.46 cw(c1512.22,4970.55) 1517.13,4970.55 1517.13,4955.82 cw(c1512.22,4955.82) 1512.22,4950.91 1472.04,4950.91 ccw(c1472.04,4946) 1467.13,4946 1467.13,4931.27 ccw(c1472.04,4931.27) 1472.04,4926.36 1512.22,4926.36 cw(c1512.22,4921.45) 1517.13,4921.45 1517.13,4906.72 cw(c1512.22,4906.72) 1512.22,4901.81 1472.04,4901.81 ccw(c1472.04,4896.9) 1467.13,4896.9 1467.13,4882.17 ccw(c1472.04,4882.17) 1472.04,4877.26 1487.22,4877.26 cw(c1487.22,4872.35) 1492.13,4872.35 1492.13,4870.08 1492.13,4855.17 2114.06,4233.24 2114.06,3398.94 2353.55,3159.45 MC3.111@2476.77,3159.45
SZG_PORTC_S26: J11.31 MC3.108 | length 3867.4
  L1-TOP w4.55: J11.31@1165.38,5821.46 1159.66,5815.74 1159.66,5777.77 1142.2,5760.31 1110.7,5760.31 1090.55,5740.16 1090.55,5699.51 1115.15,5674.92 1299.39,5674.92 1319.14,5655.17 1651.35,5655.17 1665.42,5641.1 1665.42,5562.93 1870.08,5358.27 1870.08,4674.07 2212.48,4331.67 2212.48,3434.52 2371.75,3275.25 2498.93,3275.25 2523.58,3250.59 2523.58,3206.35 2550.02,3179.91 2614.43,3179.91 2674.26,3120.08 MC3.108@2720.08,3120.08
SZG_PORTC_S27: J11.32 MC3.109 | length 3866.4
  L1-TOP w4.55: J11.32@1165.38,5595.86 1165.38,5535.43 1165.38,5512.8 cw(c1160.47,5512.8) 1160.47,5507.89 1139.91,5507.89 ccw(c1139.91,5502.98) 1135,5502.98 1135,5488.25 ccw(c1139.91,5488.25) 1139.91,5483.34 1163.87,5483.34 cw(c1163.87,5478.43) 1168.78,5478.43 1168.78,5463.7 cw(c1163.87,5463.7) 1163.87,5458.79 1137.28,5458.79 ccw(c1137.28,5453.88) 1132.37,5453.88 1132.37,5439.15 ccw(c1137.28,5439.15) 1137.28,5434.24 1163.87,5434.24 cw(c1163.87,5429.33) 1168.78,5429.33 1168.78,5414.6 cw(c1163.87,5414.6) 1163.87,5409.69 1137.28,5409.69 ccw(c1137.28,5404.78) 1132.37,5404.78 1132.37,5390.05 ccw(c1137.28,5390.05) 1137.28,5385.14 1160.47,5385.14 cw(c1160.47,5380.23) 1165.38,5380.23 1165.38,5377.95 1165.38,5358.24 1259.84,5263.78 1392.96,5263.78 1405.51,5251.22 1405.51,5232.64 1405.51,5208.27 ccw(c1410.42,5208.27) 1410.42,5203.36 1419.05,5203.36 cw(c1419.05,5198.45) 1423.96,5198.45 1423.96,5183.72 cw(c1419.05,5183.72) 1419.05,5178.81 1385.42,5178.81 ccw(c1385.42,5173.9) 1380.51,5173.9 1380.51,5159.17 ccw(c1385.42,5159.17) 1385.42,5154.26 1425.6,5154.26 cw(c1425.6,5149.35) 1430.51,5149.35 1430.51,5134.62 cw(c1425.6,5134.62) 1425.6,5129.71 1385.42,5129.71 ccw(c1385.42,5124.8) 1380.51,5124.8 1380.51,5110.07 ccw(c1385.42,5110.07) 1385.42,5105.16 1425.6,5105.16 cw(c1425.6,5100.25) 1430.51,5100.25 1430.51,5085.52 cw(c1425.6,5085.52) 1425.6,5080.61 1385.42,5080.61 ccw(c1385.42,5075.7) 1380.51,5075.7 1380.51,5060.97 ccw(c1385.42,5060.97) 1385.42,5056.06 1425.6,5056.06 cw(c1425.6,5051.15) 1430.51,5051.15 1430.51,5036.42 cw(c1425.6,5036.42) 1425.6,5031.51 1385.42,5031.51 ccw(c1385.42,5026.6) 1380.51,5026.6 1380.51,5011.87 ccw(c1385.42,5011.87) 1385.42,5006.96 1425.6,5006.96 cw(c1425.6,5002.05) 1430.51,5002.05 1430.51,4987.32 cw(c1425.6,4987.32) 1425.6,4982.41 1385.42,4982.41 ccw(c1385.42,4977.5) 1380.51,4977.5 1380.51,4962.77 ccw(c1385.42,4962.77) 1385.42,4957.86 1425.6,4957.86 cw(c1425.6,4952.95) 1430.51,4952.95 1430.51,4938.22 cw(c1425.6,4938.22) 1425.6,4933.31 1385.42,4933.31 ccw(c1385.42,4928.4) 1380.51,4928.4 1380.51,4913.67 ccw(c1385.42,4913.67) 1385.42,4908.76 1400.6,4908.76 cw(c1400.6,4903.85) 1405.51,4903.85 1405.51,4902.42 1406.35,4901.57 2094.37,4213.56 2094.37,3392.63 2347.24,3139.76 MC3.109@2476.77,3139.76
SZG_PORTD_C2P_CLKN: J1.36 MC1.3 | length 2312.7
  L1-TOP w3.3: J1.36@2952.78,5595.86 2952.78,5559.51 2967.37,5544.91 2967.37,5535.15 v1@2984.27,5518.25 ; MC1.3@3001.97,4511.42 3001.97,4534.15 2996.63,4539.5 2996.63,4547.14 v1@3005.9,4556.42
  L8-SIG w3.15: 2702.72,5423.59 ccw(c2699.44,5420.32) 2696.16,5423.6 2686.34,5413.77 ccw(c2689.61,5410.5) 2686.34,5407.23 2748.61,5344.95 2748.61,5344.74 cw(c2737.66,5336.63) 2747.3,5326.99 2737.47,5317.17 cw(c2727.84,5326.81) 2718.18,5317.19 2675.04,5360.34 ccw(c2671.76,5357.06) 2668.49,5360.34 2658.67,5350.51 ccw(c2661.94,5347.24) 2658.67,5343.97 2700.8,5301.83 cw(c2691.16,5292.2) 2700.8,5282.56 2689.43,5271.2 2682,5263.76 2682,4960 2996.63,4645.37 2996.63,4565.7 v1@3005.9,4556.42 ; 2702.74,5423.57 2763.64,5362.67 ccw(c2773.3,5372.28) 2782.94,5362.64 2792.76,5372.46 ccw(c2783.12,5382.1) 2794.08,5390.21 2794.08,5390.42 2731.81,5452.69 cw(c2735.08,5455.97) 2731.81,5459.24 2741.63,5469.06 cw(c2744.9,5465.79) 2748.18,5469.06 2809.1,5408.14 ccw(c2818.77,5417.74) 2828.41,5408.11 2838.23,5417.93 ccw(c2828.59,5427.57) 2839.55,5435.67 2839.55,5435.89 2777.27,5498.16 cw(c2780.55,5501.43) 2777.27,5504.71 2787.1,5514.53 cw(c2790.37,5511.26) 2793.65,5514.52 ; 2793.67,5514.5 2854.57,5453.6 ccw(c2864.24,5463.21) 2873.87,5453.57 2883.7,5463.4 ccw(c2874.06,5473.03) 2885.01,5481.14 2885.01,5481.35 2822.74,5543.63 cw(c2826.01,5546.9) 2822.74,5550.17 2832.56,5560 cw(c2835.84,5556.72) 2839.12,5559.99 ; 2839.14,5559.97 2899.01,5500.1 ccw(c2908.67,5509.71) 2918.31,5500.07 2945.34,5527.1 2946.75,5528.51 2974.01,5528.51 v1@2984.27,5518.25
  other v1: 3007,4556.42 2984.27,5517.25
SZG_PORTD_C2P_CLKP: J1.34 MC1.1 | length 2264
  L1-TOP w3.3: v1@2978.35,4556.42 2987.63,4547.14 2987.63,4539.49 2982.28,4534.15 MC1.1@2982.28,4511.42
  L8-SIG w3.15: 2740.93,5339.91 cw(c2737.66,5336.63) 2740.93,5333.36 2731.11,5323.54 cw(c2727.84,5326.81) 2724.56,5323.54 2711.39,5336.71 2681.4,5366.7 ccw(c2671.76,5357.06) 2662.12,5366.7 2652.3,5356.88 ccw(c2661.94,5347.24) 2652.3,5337.6 2694.43,5295.47 cw(c2691.16,5292.2) 2694.43,5288.92 2683.07,5277.56 2673,5267.49 2673,4956.27 2948.49,4680.78 2949.61,4679.66 2955.96,4673.31 cw(c2952.69,4670.04) 2955.96,4666.77 2950.13,4660.94 ccw(c2953.4,4657.66) 2950.13,4654.39 2959.95,4644.57 ccw(c2963.23,4647.84) 2966.5,4644.57 2972.33,4650.4 cw(c2975.6,4647.12) 2978.88,4650.4 ; 2740.9,5339.94 2680,5400.83 cw(c2689.61,5410.5) 2679.98,5420.14 2689.8,5429.96 cw(c2699.44,5420.32) 2707.54,5431.28 2707.76,5431.28 2770.03,5369 ccw(c2773.3,5372.28) 2776.58,5369 2786.4,5378.83 ccw(c2783.12,5382.1) 2786.39,5385.38 ; 2786.37,5385.4 2725.47,5446.3 cw(c2735.08,5455.97) 2725.44,5465.61 2735.26,5475.43 cw(c2744.9,5465.79) 2753.01,5476.75 2753.22,5476.75 2815.5,5414.47 ccw(c2818.77,5417.74) 2822.04,5414.47 2831.87,5424.29 ccw(c2828.59,5427.57) 2831.86,5430.85 ; 2831.84,5430.87 2770.94,5491.77 cw(c2780.55,5501.43) 2770.91,5511.07 2780.73,5520.89 cw(c2790.37,5511.26) 2798.48,5522.21 2798.69,5522.21 2860.96,5459.94 ccw(c2864.24,5463.21) 2867.51,5459.94 2877.33,5469.76 ccw(c2874.06,5473.03) 2877.33,5476.31 ; 2877.3,5476.34 2816.41,5537.23 cw(c2826.01,5546.9) 2816.38,5556.54 2826.2,5566.36 cw(c2835.84,5556.72) 2843.94,5567.68 2844.16,5567.68 2905.4,5506.44 ccw(c2908.67,5509.71) 2911.95,5506.44 2938.98,5533.46 2943.03,5537.51 2974.01,5537.51 v1(2984.28,5547.78) ; v1@2978.35,4556.42 2987.63,4565.7 2987.63,4641.65 2979.99,4649.28 2978.88,4650.4
  other v1: 2977.25,4556.42
SZG_PORTD_P2C_CLKN: J1.35 MC1.32 | length 2326.4
  L1-TOP w3.3: J1.35@2952.78,5821.46 2957.03,5817.21 v1(2957.03,5771.65) ; v1(3216.54,4125.73) 3217.6,4125.73 3224.6,4132.73 3247.82,4132.73 3272.22,4157.13 3272.22,4240.13 MC1.32@3273.98,4241.89 ; MC1.32@3272.22,4239.8 3273.98,4241.56 MC1.32@3273.98,4241.89 ; MC1.32@3273.98,4241.89 3277.56,4245.47 MC1.32@3277.56,4268.11 3273.98,4264.53 MC1.32@3273.98,4241.89
  L10-BOT w3.3: v1(2957.03,5771.65) 2957.03,5769.37 2964.03,5762.37 2964.03,5738.94 2944.88,5719.8 2944.88,5704.72 2914.51,5674.35 2870.29,5674.35 2841.39,5645.46 2841.39,5569.74 2750.84,5479.19 2750.84,4615.3 2822.83,4543.31 2849.27,4516.87 2849.27,4311.23 2907.02,4253.48 3027.77,4132.73 3207.25,4132.73 3214.25,4125.73 v1(3216.54,4125.73)
SZG_PORTD_P2C_CLKP: J1.33 MC1.30 | length 2304
  L1-TOP w3.3: v1(2980.03,5771.65) 2980.03,5817.21 J1.33@2984.28,5821.46 ; v1(3216.54,4148.73) 3217.6,4148.73 3224.6,4141.73 3244.09,4141.73 3263.22,4160.85 MC1.30@3263.22,4240.13 ; MC1.30@3257.87,4268.11 MC1.30@3257.87,4245.5 ; MC1.30@3257.87,4245.47 MC1.30@3263.22,4240.13 ; MC1.30@3257.87,4245.5 MC1.30@3263.22,4240.16
  L10-BOT w3.3: v1(2980.03,5771.65) 2980.03,5769.37 2973.03,5762.37 2973.03,5735.21 2953.88,5716.07 2953.88,5701 2918.24,5665.35 2874.02,5665.35 2850.39,5641.73 2850.39,5566.01 2759.84,5475.46 2759.84,4619.03 2822.83,4556.03 2858.27,4520.6 2858.27,4314.96 2907.02,4266.21 2913.39,4259.84 3031.5,4141.73 3141.67,4141.73 3151.02,4141.73 ccw(c3151.02,4146.39) 3155.68,4146.39 3155.68,4156.26 cw(c3160.34,4156.26) 3160.34,4160.92 3174.32,4160.92 cw(c3174.32,4156.26) 3178.98,4156.26 3178.98,4146.39 ccw(c3183.64,4146.39) 3183.64,4141.73 3207.25,4141.73 3208.59,4143.07 3214.25,4148.73 v1(3216.54,4148.73)
SZG_PORTD_S0_D0P: J1.5 MC1.48 | length 2246.3
  L1-TOP w3.3: v1@3431.1,4223.11 3440.38,4232.39 3440.38,4240.03 3435.04,4245.37 MC1.48@3435.04,4268.11
  L10-BOT w3.3: v1(3425.28,5773.38) 3424.79,5772.89 3414.63,5772.89 3409,5767.27 3409,5723.27 3464.27,5668 3500,5668 3518,5650 3518,5596.5 3637.8,5476.7 3637.8,5472.15 3637.8,5454.39 cw(c3633.14,5454.39) 3633.14,5449.73 3607.49,5449.73 ccw(c3607.49,5436.07) 3593.83,5436.07 3593.83,5422.09 ccw(c3607.49,5422.09) 3607.49,5408.43 3634.6,5408.43 cw(c3634.6,5403.77) 3639.26,5403.77 3639.26,5389.79 cw(c3634.6,5389.79) 3634.6,5385.13 3602.87,5385.13 ccw(c3602.87,5371.47) 3589.21,5371.47 3589.21,5357.49 ccw(c3602.87,5357.49) 3602.87,5343.83 3634.6,5343.83 cw(c3634.6,5339.17) 3639.26,5339.17 3639.26,5325.19 cw(c3634.6,5325.19) 3634.6,5320.53 3602.87,5320.53 ccw(c3602.87,5306.87) 3589.21,5306.87 3589.21,5292.89 ccw(c3602.87,5292.89) 3602.87,5279.23 3634.6,5279.23 cw(c3634.6,5274.57) 3639.26,5274.57 3639.26,5260.59 cw(c3634.6,5260.59) 3634.6,5255.93 3602.87,5255.93 ccw(c3602.87,5242.27) 3589.21,5242.27 3589.21,5228.29 ccw(c3602.87,5228.29) 3602.87,5214.63 3634.6,5214.63 cw(c3634.6,5209.97) 3639.26,5209.97 3639.26,5195.99 cw(c3634.6,5195.99) 3634.6,5191.33 3602.87,5191.33 ccw(c3602.87,5177.67) 3589.21,5177.67 3589.21,5163.69 ccw(c3602.87,5163.69) 3602.87,5150.03 3633.14,5150.03 cw(c3633.14,5145.37) 3637.8,5145.37 3637.8,5139.22 3637.8,5122.96 3546,5031.17 3546,4577.31 3571.64,4551.66 3571.64,4456.19 3517,4401.55 3517,4374 3440.38,4297.38 3440.38,4232.39 v1@3431.1,4223.11
  other v1: 3430,4223.11
SZG_PORTD_S1_D1P: J1.6 MC1.31 | length 2263.1
  L1-TOP w3.3: v1@3273.62,4556.42 3282.9,4547.14 3282.9,4539.49 3277.56,4534.15 MC1.31@3277.56,4511.42
  L8-SIG w3.15: v1@3273.62,4556.42 3282.9,4565.7 3282.9,4826.63 3303,4846.73 3303,5118.88 3324.2,5140.08 3758.32,5140.08 3786.28,5168.03 3786.28,5410.4 3759.4,5437.28 3754.44,5442.24 3742.6,5442.24 cw(c3742.6,5455.87) 3728.97,5455.87 3728.97,5478.42 ccw(c3724.34,5478.42) 3724.34,5483.05 3710.45,5483.05 ccw(c3710.45,5478.42) 3705.82,5478.42 3705.82,5452.48 cw(c3692.19,5452.48) 3692.19,5438.85 3678.3,5438.85 cw(c3678.3,5452.48) 3664.67,5452.48 3664.67,5496.64 ccw(c3660.04,5496.64) 3660.04,5501.27 3646.15,5501.27 ccw(c3646.15,5496.64) 3641.52,5496.64 3641.52,5452.48 cw(c3627.89,5452.48) 3627.89,5438.85 3614,5438.85 cw(c3614,5452.48) 3600.37,5452.48 3600.37,5496.64 ccw(c3595.74,5496.64) 3595.74,5501.27 3581.85,5501.27 ccw(c3581.85,5496.64) 3577.22,5496.64 3577.22,5452.48 cw(c3563.59,5452.48) 3563.59,5438.85 3549.7,5438.85 cw(c3549.7,5452.48) 3536.07,5452.48 3536.07,5496.64 ccw(c3531.44,5496.64) 3531.44,5501.27 3517.55,5501.27 ccw(c3517.55,5496.64) 3512.92,5496.64 3512.92,5455.87 cw(c3499.29,5455.87) 3499.29,5442.24 3493.22,5442.24 3429.33,5442.24 3407.83,5463.73 3407.83,5540.79 3412.67,5545.63 3423.13,5545.63 v1(3425.28,5547.78)
  other v1: 3272.52,4556.42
